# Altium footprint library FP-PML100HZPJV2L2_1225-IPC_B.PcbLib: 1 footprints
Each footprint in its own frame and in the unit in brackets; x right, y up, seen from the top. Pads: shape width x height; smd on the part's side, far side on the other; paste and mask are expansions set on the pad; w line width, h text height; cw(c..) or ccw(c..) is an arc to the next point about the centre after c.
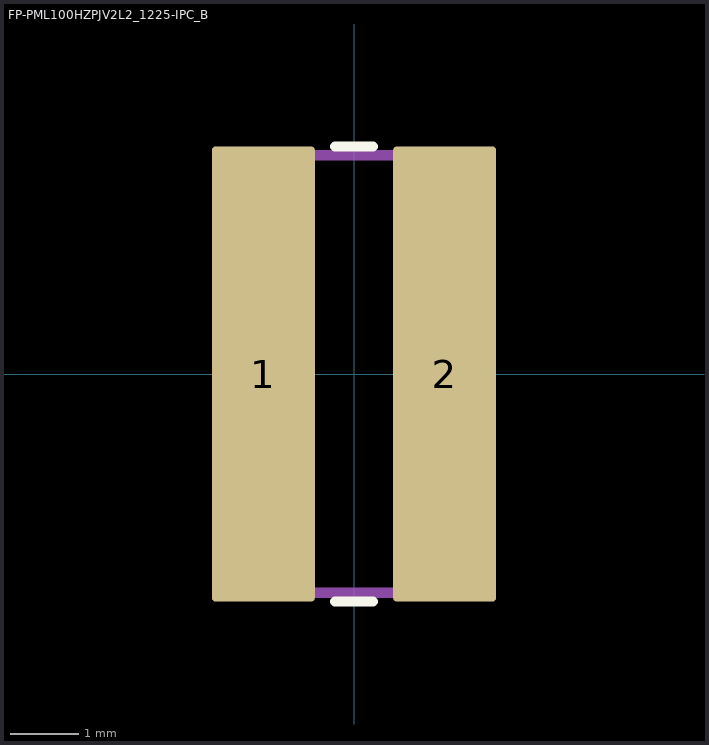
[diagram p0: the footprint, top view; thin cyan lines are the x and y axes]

## FP-PML100HZPJV2L2_1225-IPC_B [mm]
pads (2):
  rrect7% 1.505x6.655 smd paste+0 mask+0: 1(-1.325,0) 2(1.325,0)
Top Overlay:
  lines w0.15: -0.273,-3.327 0.273,-3.327 ; -0.273,3.327 0.273,3.327
Mechanical 5:
  lines w0.15: -1.6,-3.2 -1.6,3.2 1.6,3.2 1.6,-3.2 -1.6,-3.2
  text ".Designator" at 0.05,0.217 h0.5
3D body "Res_PML100HZPJV2L2_1225.STEP": height 0.25, standoff 0, extent -2.327,-3.577 2.327,3.577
